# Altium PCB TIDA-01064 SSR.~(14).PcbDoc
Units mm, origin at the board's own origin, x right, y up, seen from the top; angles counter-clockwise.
Board outline 109.22 x 50.8 mm, 2 copper layers (Top Layer, Bottom Layer), stack 1.575 mm thick; 74 components, 26 nets, 146 pads, 5 vias.
Unrouted connection lines stored in the file: 92.
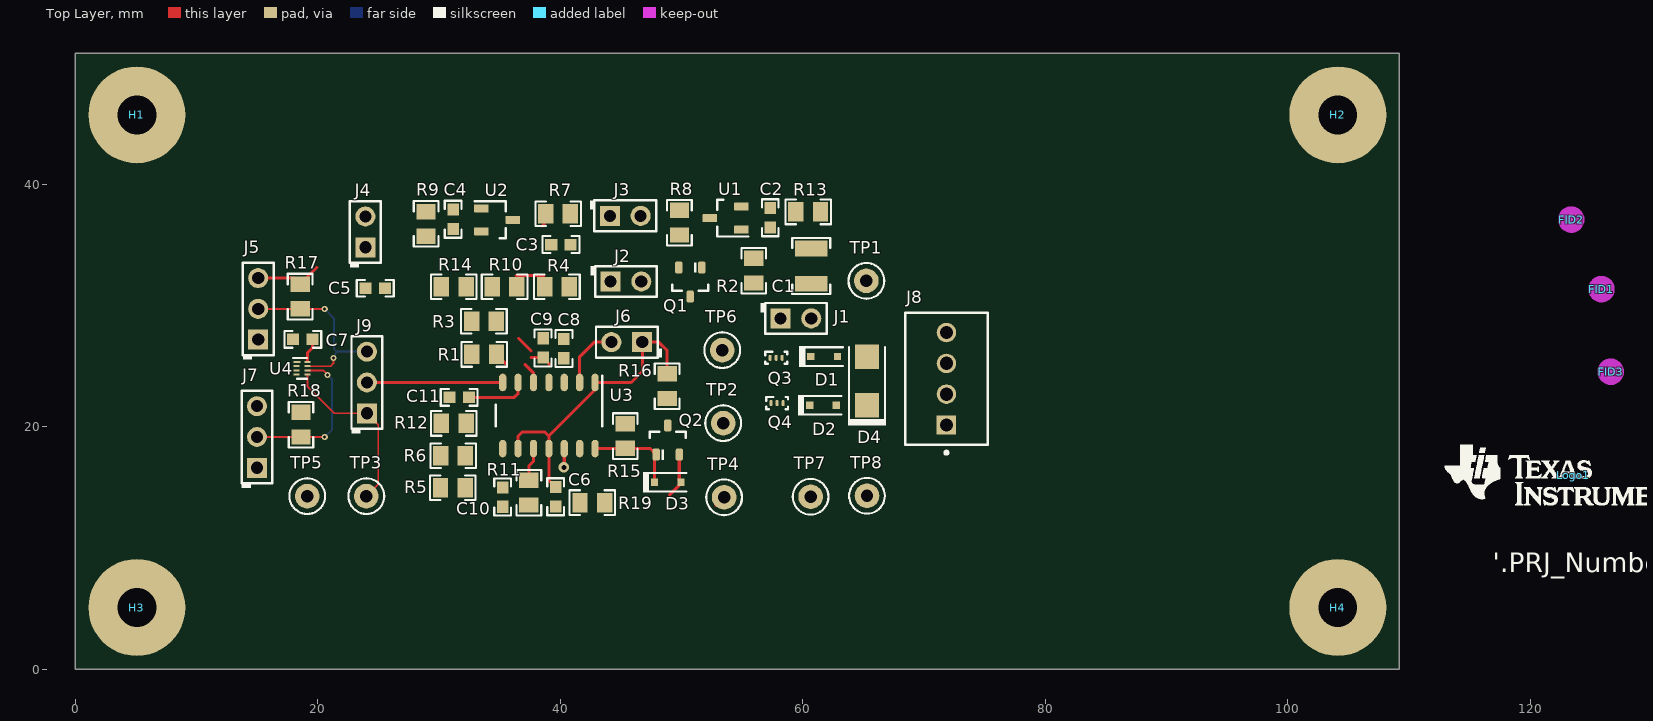
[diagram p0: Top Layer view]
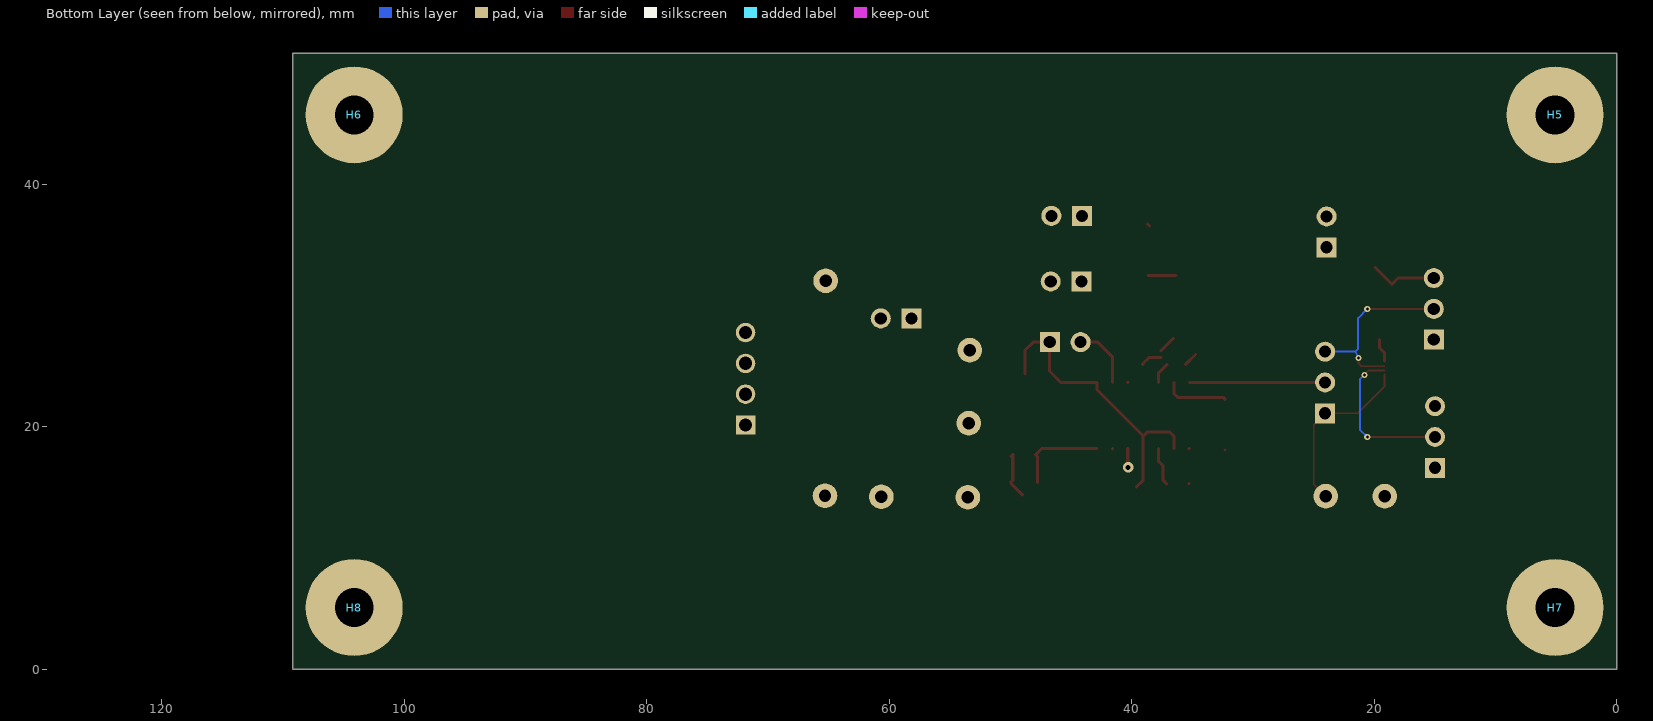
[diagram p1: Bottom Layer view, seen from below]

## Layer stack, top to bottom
Top Solder: solder mask 0.0102, Solder Resist, Dk 3.5
Top Layer: signal copper 0.0356
Dielectric1: core 1.5037, FR-4, Dk 4.8
Bottom Layer: signal copper 0.0356
Bottom Solder: solder mask 0.0102, Solder Resist, Dk 3.5

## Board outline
0,0 109.22,0 109.22,50.8 0,50.8

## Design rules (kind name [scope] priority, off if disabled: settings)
AcuteAngle [All] p1: minimum=4.50000000000000E+0001 checktracksonly=FALSE
AssemblyTestPointUsage [All] p1: valid=2
Clearance Clearance_BoardEdge_MountingHoles [OnCopper and InComponentClass('Mounting Holes') vs IsKeepOut] p1: gap=0.635
Clearance Clearance_BoardEdge_Poly [OnCopper and InPoly vs IsKeepOut] p2: gap=0.635
Clearance Clearance_BoardEdge [OnCopper and Not InComponentClass('Logo') and not InComponentClass('FiducialMark') and not InRegion(1000,500,4000,800) and Not IsKeepout vs IsKeepOut] p3: gap=0.635
Clearance Clearance_Poly [InPolygon] p4: gap=0.381
Clearance [All] p5: gap=0.203
ComponentClearance ComponentClearance_Shunt [InComponentClass('Header') vs InComponentClass('Shunt')] p1: gap=0 collisioncheckmode=3 verticalgap=0 showdistances=FALSE
ComponentClearance ComponentClearance_Logo [InComponentClass('Logo')] p2: gap=1.27 collisioncheckmode=3 verticalgap=0.254 showdistances=FALSE
ComponentClearance ComponentClearance_ScrewToNut [(HasFootprint('NY PMS 440 0025 PH')) vs (HasFootprint('Keystone_1902C'))] p3: gap=0.127 collisioncheckmode=3 verticalgap=0.254 showdistances=FALSE
ComponentClearance ComponentClearance_MountingHoles [InComponentClass('Mounting Holes')] p4: gap=6.35 collisioncheckmode=3 verticalgap=2540 showdistances=FALSE
ComponentClearance ComponentClearance_SmallPassives [HasFootprint('0201*') or HasFootprint('0402*') or HasFootprint('0508') or HasFootprint('0603*') or HasFootprint('0612') or HasFootprint('0805*') or HasFootprint('0815*') or HasFootprint('0830*') or HasFootprint('1206*') or HasFootprint('1210*') or HasFootprint('1808*') or HasFootprint('1812*') or HasFootprint('1825*') or HasFootprint('2010*') or HasFootprint('2220*') or HasFootprint('2225*') or HasFootprint('2512*') or HasFootprint('2728*') or HasFootprint('3518*') vs HasFootprint('0201*') or HasFootprint('0402*') or HasFootprint('0508') or HasFootprint('0603*') or HasFootprint('0612') or HasFootprint('0805*') or HasFootprint('0815*') or HasFootprint('0830*') or HasFootprint('1206*') or HasFootprint('1210*') or HasFootprint('1808*') or HasFootprint('1812*') or HasFootprint('1825*') or HasFootprint('2010*') or HasFootprint('2220*') or HasFootprint('2225*') or HasFootprint('2512*') or HasFootprint('2728*') or HasFootprint('3518*')] p5: gap=0.381 collisioncheckmode=3 verticalgap=0.254 showdistances=FALSE
ComponentClearance ComponentClearance_THtoSMT [IsThruComponent vs IsSMTComponent] p6: gap=1.27 collisioncheckmode=3 verticalgap=0.762 showdistances=FALSE
ComponentClearance ComponentClearance_THtoTH [IsThruComponent vs IsThruComponent] p7: gap=1.27 collisioncheckmode=3 verticalgap=0.762 showdistances=FALSE
ComponentClearance [All] p8: gap=1.016 collisioncheckmode=3 verticalgap=0.254 showdistances=FALSE
DiffPairsRouting [All] p1: maxlimit=2.54 minlimit=0.254 mostfreqgap=0.254 toplayer_minwidth=0.381 toplayer_maxwidth=0.381 toplayer_prefwidth=0.381 bottomlayer_minwidth=0.381 bottomlayer_maxwidth=0.381 bottomlayer_prefwidth=0.381 maxuncoupledlength=25.4
FabricationTestPointUsage TestPointUsage [All] p1: valid=2 allowmultiple=FALSE
FabricationTestpoint Testpoint [All] p1: side=3 testpointundercomponent=TRUE minsize=1.016 maxsize=2.54 preferedsize=1.524 minholesize=0 maxholesize=1.016 preferedholesize=0.813 testpointgrid=0.025 allowsidetop=TRUE allowsidebottom=TRUE usegrid=TRUE gridtolerance=0
FanoutControl Fanout_LCC [IsLCC] p1: bgadir=Out bgaviamode=Centered fanoutstyle=Auto fanoutdirection=Alternating viagrid=0.025 // Fanout_LCC (Default Rule)
FanoutControl Fanout_BGA [IsBGA] p2: bgadir=Out bgaviamode=Centered fanoutstyle=Auto fanoutdirection=Alternating viagrid=0.025 // Fanout_BGA (Default Rule)
FanoutControl Fanout_Default [All] p4: bgadir=Out bgaviamode=Centered fanoutstyle=Auto fanoutdirection=Alternating viagrid=0.025 // Fanout_Default (Default Rule)
FanoutControl Fanout_Small [(CompPinCount < 5)] p5: bgadir=Out bgaviamode=Centered fanoutstyle=Auto fanoutdirection=OutThenIn viagrid=0.025 // Fanout_Small (Default Rule)
HoleSize [All] p1: absolutevalues=TRUE maxlimit=6.375 minlimit=0.203 maxpercent=80.000 minpercent=20.000
MinimumAnnularRing MinimumAnnularRing_ThermalPadVias [IsVia and InAnyComponent] p1: minimumring=0.15
MinimumAnnularRing [All] p2: minimumring=0.229
MinimumSolderMaskSliver MinimumSolderMaskSliver_Logo [InComponentClass('Logo') vs InComponentClass('Logo')] p1: minsoldermaskwidth=0.018
MinimumSolderMaskSliver [All] p2: minsoldermaskwidth=0.1
PlaneClearance [All] p1: clearance=0.381
PlaneConnect [All] p1: planeconnectstyle=Direct reliefexpansion=0.254 reliefentries=4 reliefconductorwidth=0.254 reliefairgap=0.254
PolygonConnect [All] p1: connectstyle=Direct reliefconductorwidth=0.254 reliefentries=4 polygonreliefangle="90 Angle" airgapwidth=0.254
RoutingVias ThermalPadVias [IsVia and InAnyComponent] p1: holewidth=0.2 width=0.5 viastyle="Through Hole" minholewidth=0.2 minwidth=0.5 maxholewidth=0.33 maxwidth=0.6
RoutingVias [All] p2: holewidth=0.406 width=0.864 viastyle="Through Hole" minholewidth=0.2 minwidth=0.66 maxholewidth=1.016 maxwidth=1.651
SMDToCorner [All] p1: distance=30000
SilkToBoardRegionClearance [Not ((IsComment or IsDesignator) And (Hide <> 'False')) and not InRegion(1000,500,4000,800)] p1:
SilkToSilkClearance [All] p1: silktosilkclearance=0
SilkToSolderMaskClearance SilkscreenOverComponentPads [IsPad] p1: minsilkscreentomaskgap=0 clearancetoexposedcopper=TRUE
SolderMaskExpansion [All] p1: expansion=0.05
Width [All] p1: maxlimit=2.54 minlimit=0.152 preferedwidth=0.254 checkconnectedcopper=TRUE
14 further rules are at their usual default settings.

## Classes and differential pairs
component class "TIDA-01064 SSR_Relay": C1 C2 C3 C4 C6 C7 C8 C9 C10 C11 D1 D2 D3 D4 J1 J2 J3 J4 J5 J6 J7 J8 J9 Q1 Q2 Q3 Q4 R1 R2 R3 R4 R5 R6 R7 R8 R9 R10 R11 R12 R13 R14 R15 R16 R17 R18 R19 TP1 TP2 TP3 TP4 TP5 TP6 TP7 TP8 U1 U2 U3 U4
component class Header: J1 J2 J3 J4 J5 J6 J7 J9
component class "Mounting Holes": H1 H2 H3 H4
component class Logo: Logo1
component class "TIDA-01064 SSR_TID_Hardware": FID1 FID2 FID3 H1 H2 H3 H4 H5 H6 H7 H8 Logo1 ZZ1 ZZ2
component class FiducialMark: FID1 FID2 FID3
component class AssemblyNote: ZZ1 ZZ2

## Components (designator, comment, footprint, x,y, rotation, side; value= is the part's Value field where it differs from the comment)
C1 "C3225X7S2A335M200AB" 1210 60.706,33.249 r90 top
C2 "GRM1885C1H201JA01D" 0603 57.328,37.236 r90 top
C3 "GRM188R61E105KA12D" 0603 40.056,35.027 r180 top
C4 "GRM1885C1H201JA01D" 0603 31.166,37.109 r270 top
C5 "GRM188R61E105KA12D" 0603 24.74,31.42 r0 top
C6 "GRM188R61E105KA12D" 0603 39.624,14.224 r270 top
C7 "GRM188R71C104KA01D" 0603 18.771,27.203 r0 top
C8 "GRM188R71C104KA01D" 0603 40.31,26.441 r270 top
C9 "GRM188R71C104KA01D" 0603 38.583,26.492 r270 top
C10 "GRM188R71C104KA01D" 0603 35.255,14.199 r90 top
C11 "GRM188R71C104KA01D" 0603 31.666,22.42 r0 top
D1 "1N4448WX-TP" sod-323 61.773,25.781 r0 top
D2 "1N4448WX-TP" sod-323 61.671,21.768 r0 top
D3 "1N4448WX-TP" sod-323 48.87,15.418 r0 top
D4 "SMAJ40CA" SMA 65.303,23.774 r90 top
FID1 "Fiducial" Fiducial10-20 125.882,31.344 r0 top
FID2 "Fiducial" Fiducial10-20 123.393,37.084 r0 top
FID3 "Fiducial" Fiducial10-20 126.644,24.536 r0 top
H1 "NY PMS 440 0025 PH" "NY PMS 440 0025 PH" 5.08,45.72 r0 top locked
H2 "NY PMS 440 0025 PH" "NY PMS 440 0025 PH" 104.14,45.72 r0 top locked
H3 "NY PMS 440 0025 PH" "NY PMS 440 0025 PH" 5.08,5.08 r0 top locked
H4 "NY PMS 440 0025 PH" "NY PMS 440 0025 PH" 104.14,5.08 r0 top locked
H5 "1902C" Keystone_1902C 5.08,45.72 r180 bottom locked
H6 "1902C" Keystone_1902C 104.14,45.72 r180 bottom locked
H7 "1902C" Keystone_1902C 5.08,5.08 r180 bottom locked
H8 "1902C" Keystone_1902C 104.14,5.08 r180 bottom locked
J1 "5-146278-2" TE_5-146278-2 59.436,28.931 r0 top
J2 "5-146278-2" TE_5-146278-2 45.415,31.979 r0 top
J3 "5-146278-2" TE_5-146278-2 45.364,37.389 r0 top
J4 "5-146278-2" TE_5-146278-2 23.927,36.068 r90 top
J5 "5-146278-3" TE_5-146278-3 15.088,29.718 r90 top
J6 "5-146278-2" TE_5-146278-2 45.491,26.975 r180 top
J7 "5-146278-3" TE_5-146278-3 14.987,19.152 r90 top
J8 "282834-4" TEC_282834-4 71.857,23.952 r90 top
J9 "5-146278-3" TE_5-146278-3 24.054,23.647 r90 top
Logo1 "Texas Instruments" TI_Stacked_Overlay_Small 123.571,16.002 r0 top
Q1 "MMBTA05LT1G" SOT-23 50.724,31.928 r270 top
Q2 "MMBT3904LT1G" SOT-23 48.87,18.898 r90 top
Q3 "CSD18541F5" YJK0003A 57.81,25.679 r0 top
Q4 "CSD18541F5" YJK0003A 57.887,21.946 r0 top
R1 "CRCW080510M0FKEA" 0805_HV 33.724,25.959 r0 top
R2 "CRCW0805205KFKEA" 0805_HV 55.956,32.868 r270 top
R3 "CRCW08053M09FKEA" 0805_HV 33.706,28.702 r0 top
R4 "CRCW080510M0FKEA" 0805_HV 39.726,31.547 r0 top
R5 "CRCW080510M0FKEA" 0805_HV 31.14,14.961 r180 top
R6 "RC0805JR-0733ML" 0805_HV 31.166,17.602 r180 top
R7 "CRCW0805100KFKEA" 0805_HV 39.827,37.567 r0 top
R8 "CRCW08053M74FKEA" 0805_HV 49.835,36.83 r270 top
R9 "CRCW0805806KFKEA" 0805_HV 28.931,36.728 r90 top
R10 "CRCW08057M50FKEA" 0805_HV 35.408,31.547 r0 top
R11 "CRCW08054M32FKEA" 0805_HV 37.414,14.554 r90 top
R12 "CRCW08056M49FKEA" 0805_HV 31.217,20.269 r0 top
R13 "CRCW08051M30FKEA" 0805_HV 60.452,37.719 r180 top
R14 "CRCW08052M80FKEA" 0805_HV 31.217,31.547 r180 top
R15 "CRCW080590K9FKEA" 0805_HV 45.364,19.228 r90 top
R16 "CRCW08051M82FKEA" 0805_HV 48.819,23.343 r270 top
R17 "CRCW0805124KFKEA" 0805_HV 18.542,30.734 r90 top
R18 "CRCW0805124KFKEA" 0805_HV 18.618,20.168 r90 top
R19 "CRCW08050000Z0EA" 0805_HV 42.647,13.741 r0 top
TP1 "5001" Keystone5001 65.253,32.029 r0 top
TP2 "5001" Keystone5001 53.442,20.295 r0 top
TP3 "5001" Keystone5001 24.007,14.272 r0 top
TP4 "5001" Keystone5001 53.518,14.173 r0 top
TP5 "5001" Keystone5001 19.131,14.272 r0 top
TP6 "5001" Keystone5001 53.365,26.314 r0 top
TP7 "5001" Keystone5001 60.655,14.224 r0 top
TP8 "5001" Keystone5001 65.303,14.3 r0 top
U1 "ATL431AIDBZR" DBZ0003A_M 53.645,37.211 r180 top
U2 "ATL431AIDBZR" DBZ0003A_M 34.798,37.059 r0 top
U3 "LP339D" D0014A_N 39.065,20.922 r270 top
U4 "SN74AUP1G74DQER" DQE0008A 18.694,24.816 r0 top
ZZ1 "These assemblies are ESD sensitive, ESD precautions shall be observed." AssemblyNote 4.699,97.259 r0 top
ZZ2 "These assemblies must be clean and free from flux and all contaminants. Use of no clean flux is not acceptable." AssemblyNote 4.699,95.01 r0 top
ZZ3 "These assemblies must comply with workmanship standards IPC-A-610 Class 2, unless otherwise specified." AssemblyNote 4.699,92.761 r0 top

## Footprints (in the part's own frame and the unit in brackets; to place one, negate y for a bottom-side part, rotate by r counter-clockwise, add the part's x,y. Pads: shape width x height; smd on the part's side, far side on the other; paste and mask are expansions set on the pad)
0603 [mm] "0603 from SM-752 data"
  rect 1x0.95 smd: 1(-0.8,0) 2(0.8,0)
  silkscreen extent -1.52,-0.69 1.52,0.69, body extent -0.87,-0.47 0.87,0.47, height 1
0805_HV [mil] "0805 with 30mil clearance between pads"
  rect 50x63 smd: 1(-40,0) 2(40,0)
  silkscreen extent -74,-40 74,40, body extent -43,-29 43,29, height 57
1210 [mm] "1210 from SM-752 data"
  rect 1.3x2.7 smd: 1(-1.45,0) 2(1.45,0)
  silkscreen extent -2.32,-1.57 2.32,1.57, body extent -1.7,-1.35 1.7,1.35, height 1.35
AssemblyNote [mm] "Assembly Note"
D0014A_N [mm] "SOIC, 14-Leads, Body 8.7x3.9mm, Pitch 1.27mm, IPC Medium Density"
  oval 1.45x0.6 smd: 1(-2.725,3.81) 2(-2.725,2.54) 3(-2.725,1.27) 4(-2.725,0) 5(-2.725,-1.27) 6(-2.725,-2.54) 7(-2.725,-3.81) 8(2.725,-3.81) 9(2.725,-2.54) 10(2.725,-1.27) 11(2.725,0) 12(2.725,1.27) 13(2.725,2.54) 14(2.725,3.81)
  silkscreen extent -3.3,-4.4 0.9,4.4, body extent -3.02,-4.32 3.02,4.32, height 1.6
DBZ0003A_M [mm] "SOT23, 3-Leads, Body 2.9x1.3mm, Pitch 0.95mm, Lead Span 2.4mm, IPC Low Density"
  rrect15% 1.2x0.65 smd: 1(-1.3,0.95) 2(-1.3,-0.95) 3(1.3,0)
  silkscreen extent -1.85,-1.5 0.7,1.53, body extent -1.26,-1.46 1.26,1.46, height 0.98
DQE0008A [mm] "SON, 8-Leads, Body 1.4x1mm, Pitch 0.35mm, TI Recommended"
  rect 0.6x0.16 smd mask+0: 1(-0.4,0.525)
  rect 0.5x0.16 smd mask+0: 2(-0.45,0.175) 3(-0.45,-0.175) 4(-0.45,-0.525) 5(0.45,-0.525) 6(0.45,-0.175) 7(0.45,0.175) 8(0.45,0.525)
  silkscreen extent -0.7,-0.85 0.4,0.85, body extent -0.53,-0.72 0.53,0.73, height 0.41
Fiducial10-20 [mm]
  round 1 smd mask+0.5: 1(0,0)
  Top Layer keep-out circle w1.178: c0,0 r0.5
Keystone5001 [mil] "For Keystone 500x miniature loop terminals"
  round 80 hole 40: 1(0,0)
  silkscreen extent -58,-58 58,58, body extent -49,-49 49,49, height 182
Keystone_1902C [mm] "Hex Standoff, 4-40 threaded, nylon"
  body extent -3.68,-3.2 3.71,3.2, height 12.73
"NY PMS 440 0025 PH" [mm] "4-40 nylon screw and mounting hole"
  round 8 hole 3.2: 1(0,0)
  body extent -3.3,-3.3 3.3,3.3, height 2.69
SMA [mm] "Molded Diode, 2-Leads, Body 4.3x2.6mm, IPC Medium Density, based on OnSemi component dimensions and land pattern"
  rect 2x2 smd: 1(-2,0) 2(2,0)
  silkscreen extent -3.66,-1.57 2.79,1.57, body extent -2.6,-1.3 2.6,1.3, height 2.42
sod-323 [mm] "NXP recommended land pattern"
  rect 0.6x0.6 smd paste-0.05: 1(-1.1,0) 2(1.1,0)
  silkscreen extent -2.06,-0.86 1.53,0.86, body extent -1.3,-0.67 1.3,0.68, height 1.1
SOT-23 [mm] "SOT23, 3-Leads, Body 2.9x1.3mm, Pitch 0.95mm, Lead Span 2.5mm, IPC Medium Density"
  rrect50% 1x0.6 smd: 1(-1.2,0.95) 2(-1.2,-0.95) 3(1.2,0)
  silkscreen extent -1.63,-1.5 0.7,1.5, body extent -1.16,-1.45 1.21,1.45, height 1
TE_5-146278-2 [mm] "TE CONNECTIVITY"
  rect 1.65x1.65 hole 1: 1(-1.27,0)
  round 1.65 hole 1: 2(1.27,0)
  silkscreen extent -2.92,-1.27 2.54,1.27, body extent -2.41,-1.17 2.41,1.17, height 8.13
TE_5-146278-3 [mm] "TE CONNECTIVITY"
  rect 1.65x1.65 hole 1: 1(-2.54,0)
  round 1.65 hole 1: 2(0,0) 3(2.54,0)
  silkscreen extent -4.19,-1.27 3.81,1.27, body extent -3.68,-1.17 3.68,1.17, height 8.13
TEC_282834-4 [mm] "TEC"
  rect 1.6x1.6 hole 1.1: 1(-3.81,0)
  round 1.6 hole 1.1: 2(-1.27,0) 3(1.27,0) 4(3.81,0)
  silkscreen extent -6.2,-3.4 5.44,3.4, body extent -5.31,-3.25 5.31,3.25, height 10.02
TI_Stacked_Overlay_Small [mm]
  silkscreen extent -10.63,-2.49 10.63,2.49
YJK0003A [mm] "SMD, 3-Leads, Body 1.49x0.73mm"
  rrect80% 0.25x0.49 smd paste-0.05 mask-0.05: 1(-0.5,0) 2(0,0) 3(0.5,0)
  silkscreen extent -0.9,-0.5 0.9,0.5, body extent -0.75,-0.37 0.74,0.36, height 0.35

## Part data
C1: "CAP, CERM, 3.3 µF, 100 V, +/- 20%, X7S, 1210"
C2 C4: "CAP, CERM, 200 pF, 50 V, +/- 5%, C0G/NP0, 0603"
C3 C5 C6: "CAP, CERM, 1 µF, 25 V, +/- 10%, X5R, 0603"
C7 C8 C9 C10 C11: "CAP, CERM, 0.1 µF, 16 V, +/- 10%, X7R, 0603"
D1 D2 D3: "Diode, Switching, 75 V, 0.25 A, SOD-323"
D4: "Diode, TVS, Bi, 40 V, 400 W, SMA"
FID1 FID2 FID3: "Fiducial mark.  There is nothing to buy or mount."
H1 H2 H3 H4: "Machine Screw, Round, #4-40 x 1/4, Nylon, Philips panhead"
H5 H6 H7 H8: "Standoff, Hex, 0.5\"L #4-40 Nylon"
J1 J2 J3 J4 J6: "Header, 100mil, 2x1, Tin, TH"
J5 J7 J9: "Header, 100mil, 3x1, Tin, TH"
J8: "Terminal Block, 100mil, 4X1 TH"
Logo1: library part TI_Logo, "Texas Instrument Corporate Signature"
Q1: library part "MMBTA05LT1G, ON Semiconductor", "Transistor, NPN, 60 V, 0.5 A, AEC-Q101, SOT-23"
Q2: library part "MMBT3904LT1G, ON Semiconductor", "Transistor, NPN, 40 V, 0.2 A, SOT-23"
Q3 Q4: "MOSFET, N-CH, 60 V,  A, PICOSTAR-3"
R1 R4 R5: "RES, 10.0 M, 1%, 0.125 W, 0805"
R2: "RES, 205 k, 1%, 0.125 W, 0805"
R3: "RES, 3.09 M, 1%, 0.125 W, 0805"
R6: "RES, 33 M, 5%, 0.125 W, 0805"
R7: "RES, 100 k, 1%, 0.125 W, 0805"
R8: "RES, 3.74 M, 1%, 0.125 W, 0805"
R9: "RES, 806 k, 1%, 0.125 W, 0805"
R10: "RES, 7.50 M, 1%, 0.125 W, 0805"
R11: "RES, 4.32 M, 1%, 0.125 W, 0805"
R12: "RES, 6.49 M, 1%, 0.125 W, 0805"
R13: "RES, 1.30 M, 1%, 0.125 W, 0805"
R14: "RES, 2.80 M, 1%, 0.125 W, 0805"
R15: "RES, 90.9 k, 1%, 0.125 W, 0805"
R16: "RES, 1.82 M, 1%, 0.125 W, 0805"
R17 R18: "RES, 124 k, 1%, 0.125 W, 0805"
R19: "RES, 0, 5%, 0.125 W, 0805"
TP1 TP2 TP3 TP4 TP5 TP6 TP7 TP8: "Test Point, Miniature, Black, TH"
U1 U2: "2.5V Low Iq Adjustable Precision Shunt Regulator, DBZ0003A"
U3: "Quad, Low-Power, General Purpose Differential Comparator, D0014A"
U4: "LOW-POWER SINGLE POSITIVE-EDGE-TRIGGERED D-TYPE FLIP-FLOP WITH CLEAR AND PRESET, DQE0008A"
ZZ1 ZZ2 ZZ3: library part AssemblyNote

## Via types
v1: diameter 0.508, hole 0.254, Top Layer to Bottom Layer, 4 vias
v2: diameter 0.864, hole 0.406, Top Layer to Bottom Layer, 1 vias

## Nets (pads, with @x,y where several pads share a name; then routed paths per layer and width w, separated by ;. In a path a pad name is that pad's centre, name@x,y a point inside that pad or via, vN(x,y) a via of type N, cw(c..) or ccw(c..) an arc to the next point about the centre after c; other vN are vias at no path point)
3.3V: C5.1 C7.2 J4.1 J5.3 J7.3 R17.2 R18.2 U4.8 | length 7.6
  Top Layer w0.254: J5.3 18.034,32.258 R17.2 19.939,33.147 ; U4.8@19.144,25.401 19.144,26.074 19.571,26.5 C7.2
10V: C3.1 C8.2 J3.1 Q2.3 R4.2 R5.2 R6.2 R7.2 R15.2 R16.2 U3.3 | length 0
  Top Layer w0.254: U3.3@40.31,23.672 U3.3
GND: C1.2 C3.2 C5.2 C6.2 C7.1 C8.1 C9.1 C10.1 C11.1 J5.1 J7.1 Q3.2 Q4.3 R3.1 R10.1 R11.1 R12.1 R13.1 R14.1 TP5.1 TP6.1 TP7.1 U1.3 U2.3 U3.12 U4.1 U4.2 U4.4 | length 1.6
  Top Layer w0.254: v2(40.31,16.637) 40.335,16.662 U3.12
HV1: D1.2 D4.2 J8.3 J8.4 Q3.3 TP1.1
HV2: D2.2 D4.1 J8.1 J8.2 Q4.2 TP8.1
NetC1_1: C1.1 J1.1 J2.2 Q1.3 R2.2
NetC2_1: C2.1 Q1.1 R2.1 U1.1
NetC2_2: C2.2 R8.1 R13.2 U1.2
NetC4_1: C4.1 J4.2 R7.1 R9.2 U2.1 | length 0.2
  Top Layer w0.254: 38.542,36.561 38.71,36.728
NetC4_2: C4.2 R9.1 R14.2 U2.2
NetC6_1: C6.1 J6.1 R16.1 U3.1 U3.9 U3.11 | length 25.2
  Top Layer w0.254: U3.9 36.525,19.228 36.855,19.558 38.735,19.558 39.065,19.228 ; C6.1 39.065,15.583 U3.11 39.065,19.228 ; R16.1 48.819,26.289 48.133,26.975 J6.1 46.787,26.949 46.787,24.587 45.846,23.647 U3.1 42.875,23.038 39.065,19.228
NetD1_1: D1.1 D2.1 J1.2
NetD3_1: D3.1 Q2.1 R15.1 TP2.1 U3.14 | length 7.6
  Top Layer w0.254: U3.14 45.349,18.197 R15.1 47.405,18.212 Q2.1 47.77,17.548 D3.1 ; TP2.1@53.416,20.269 TP2.1
NetD3_2: D3.2 Q2.2 Q3.1 Q4.1 R19.2 TP4.1 | length 5
  Top Layer w0.254: 48.997,14.351 49.97,15.324 D3.2 49.82,15.568 Q2.2 Q2.2@49.97,17.548 ; TP4.1@52.832,13.487 TP4.1
NetJ2_1: J2.1 R1.1
NetJ3_2: J3.2 Q1.2 R8.2
NetJ6_2: J6.2 U3.2 | length 5.2
  Top Layer w0.254: U3.2 41.605,25.781 42.799,26.975 J6.2
NetJ9_1: J9.1 TP3.1 U4.5 | length 14.4
  Top Layer w0.152: U4.5 19.144,23.324 21.361,21.107 J9.1 24.994,20.168 24.994,15.258 TP3.1
NetJ9_2: J9.2 U3.7 | length 11.2
  Top Layer w0.254: J9.2 U3.7
NetR19_1: R19.1 U3.13 | length 0
  Top Layer w0.254: U3.13@41.58,18.171 U3.13
OFF#: J7.2 R18.1 U4.6 | length 12.9
  Top Layer w0.152: J7.2 R18.1 v1(20.574,19.152) ; U4.6 20.444,24.641 v1(20.815,24.27)
  Bottom Layer w0.152: v1(20.574,19.152) 21.184,19.761 21.184,23.901 v1(20.815,24.27)
ON#: J5.2 J9.3 R17.1 U4.7 | length 15.2
  Top Layer w0.152: J5.2 R17.1 v1(20.574,29.718) ; U4.7 21.054,24.991 21.285,25.222 v1(21.285,25.679)
  Bottom Layer w0.152: v1(20.574,29.718) 21.336,28.956 21.336,26.416 21.565,26.187 ; v1(21.285,25.679) 21.565,26.187 ; J9.3 21.565,26.187
VREF1: C9.2 R4.1 R10.2 U3.4 | length 5.5
  Top Layer w0.254: 36.373,32.487 38.659,32.487 ; 36.576,27.28 37.592,26.264 ; 37.592,25.705 38.57,25.705 C9.2 39.111,25.163 39.065,25.117
VREF2: C10.2 R5.1 R11.2 U3.8 U3.10 | length 3.3
  Top Layer w0.254: U3.8 U3.8@35.292,18.16 ; C10.2@35.28,15.291 C10.2@35.292,15.279 ; R11.2@37.123,15.279 R11.2 37.414,16.764 37.795,17.145 U3.10
VREF3: C11.2 R6.1 R12.2 U3.6 | length 5.3
  Top Layer w0.254: C11.2@32.301,22.255 C11.2 36.212,22.42 36.525,22.733 U3.6
VUVLO: R1.2 R3.2 U3.5 | length 3
  Top Layer w0.254: R1.2 35.553,25.146 ; 37.084,25.146 37.776,24.454 37.795,24.454 U3.5
pads on no net: FID1.1 FID2.1 FID3.1 H1.1 H2.1 H3.1 H4.1 U4.3

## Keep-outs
Keep-Out Layer:
  text ".Layer_Name" at 14.656,-21.806 h1.52

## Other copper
Top Layer:
  text ".Layer_Name" at 14.656,-21.806 h1.52
Bottom Layer:
  text ".Layer_Name" at 14.656,-21.806 h1.52

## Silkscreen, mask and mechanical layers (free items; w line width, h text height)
Top Overlay:
  text "'.PRJ_Number' .PCB_Rev" at 116.916,7.468 h2.75
  text ".Layer_Name" at 14.656,-21.806 h1.52
Bottom Overlay:
  text ".Layer_Name" at 14.656,-21.806 h1.52
Top Paste:
  text ".Layer_Name" at 14.656,-21.806 h1.52
Bottom Paste:
  text ".Layer_Name" at 14.656,-21.806 h1.52
Top Solder:
  text ".Layer_Name" at 14.656,-21.806 h1.52
  text ".Layer_Name" at 14.656,-21.806 h1.52
Bottom Solder:
  text ".Layer_Name" at 14.656,-21.806 h1.52
Drill Guide:
  text ".Layer_Name" at 14.656,-21.806 h1.52
M1 Board Outline:
  the board outline again, w0.254
  text ".Layer_Name" at 14.656,-21.806 h1.52
M2 Board Dimensions:
  rectangle: 0,-6.985 3.175,-3.81
  rectangle: 3.175,-10.16 12.7,-6.985
  lines w0.178: 0,-6.985 25.4,-6.985 ; 3.175,-10.16 3.175,-3.81 ; 6.35,-10.16 6.35,-3.81 ; 12.7,-10.16 12.7,-3.81 ; 19.05,-10.16 19.05,-3.81 ; 0,-10.16 25.4,-10.16 25.4,-3.81 0,-3.81 0,-10.16
  text ".Layer_Name" at 14.656,-21.806 h1.52
M3 3D STEP Top:
  text ".Layer_Name" at 14.656,-21.806 h1.52
M4 3D STEP Bottom:
  text ".Layer_Name" at 14.656,-21.806 h1.52
M5 Assembly Top:
  lines w0.254: -7.417,-23.626 160.223,-23.626 ; -7.417,-18.462 160.274,-18.462 ; -7.417,-13.297 -7.417,-28.791 94.31,-28.791 160.274,-28.791 160.274,-13.297 -7.404,-13.297 -7.404,-28.791 32.614,-28.791 ; 55.194,-28.791 55.194,-13.297 ; 87.376,-18.462 87.376,-13.297 ; 108.712,-18.462 108.712,-13.297 ; 124.511,-28.956 124.511,-23.804
  text "COMPONENTS MARKED 'DNP' SHOULD NOT BE POPULATED." at 29.299,-8.09 h1.52
  text "ASSEMBLY VARIANT:" at 29.286,-11.024 h1.52
  text ".VariantName" at 55.601,-11.024 h1.52
  text "PCB VIEWED FROM TOP SIDE" at -5.804,-16.654 h1.52
  text "BOARD #:" at 57.099,-16.654 h1.52
  text ".PRJ_Number" at 70.955,-16.654 h1.52
  text "REV:" at 92.405,-16.654 h1.52
  text ".PCB_Rev" at 99.809,-16.654 h1.52
  text "SVN REV:" at 113.69,-16.654 h1.52
  text ".VersionControl_RevNumber" at 126.543,-16.654 h1.52
  text "TID #:" at 57.099,-21.819 h1.52
  text ".TID" at 70.955,-21.819 h1.52
  text "PLOT NAME =" at -5.804,-27.034 h1.52
  text ".plot_File_Name" at 14.656,-27.034 h1.52
  text "GENERATED    :" at 57.15,-27.034 h1.52
  text ".Print_Date" at 79.235,-27.034 h1.52
  text ".Print_Time" at 97.752,-27.034 h1.52
  text "TEXAS INSTRUMENTS" at 129.87,-27.034 h1.52
M6 Assembly Bottom:
  lines w0.254: -7.429,-18.474 160.261,-18.474 ; -7.379,-23.639 160.261,-23.639 ; 28.334,-28.969 28.334,-23.817 ; 44.133,-18.474 44.133,-13.31 ; 65.468,-18.474 65.468,-13.31 ; 97.65,-28.804 97.65,-13.31 ; 120.231,-28.804 160.249,-28.804 160.249,-13.31 -7.429,-13.31 -7.429,-28.804 58.534,-28.804 160.261,-28.804 160.261,-13.31
  text "COMPONENTS MARKED 'DNP' SHOULD NOT BE POPULATED." at 154.991,-8.077 h1.52
  text ".VariantName" at 128.473,-11.024 h1.52
  text "ASSEMBLY VARIANT:" at 154.864,-11.024 h1.52
  text ".VersionControl_RevNumber" at 26.302,-16.667 h1.52
  text "SVN REV:" at 39.154,-16.667 h1.52
  text ".PCB_Rev" at 53.035,-16.667 h1.52
  text "REV:" at 60.439,-16.667 h1.52
  text ".PRJ_Number" at 81.89,-16.667 h1.52
  text "BOARD #:" at 95.745,-16.667 h1.52
  text "PCB VIEWED FROM BOTTOM SIDE" at 158.648,-16.667 h1.52
  text ".TID" at 81.89,-21.831 h1.52
  text "TID #:" at 95.745,-21.831 h1.52
  text "TEXAS INSTRUMENTS" at 22.974,-27.047 h1.52
  text ".Print_Time" at 55.093,-27.047 h1.52
  text ".Print_Date" at 73.609,-27.047 h1.52
  text "GENERATED    :" at 95.694,-27.047 h1.52
  text ".plot_File_Name" at 138.189,-27.047 h1.52
  text "PLOT NAME =" at 158.648,-27.047 h1.52
M9 Title Sheet:
  drawing of 57 lines, arcs and shapes, not listed
  text "1" at 18.792,204.127 h1.78
  text "2" at 82.182,204.127 h1.78
  text "3" at 145.411,204.127 h1.78
  text "4" at 209.08,204.127 h1.78
  text "5" at 272.555,204.127 h1.78
  text "6" at 336.182,204.127 h1.78
  text "A" at -10.579,175.095 h1.78
  text "A" at 365.341,175.095 h1.78
  text "B" at -10.579,114.643 h1.78
  text "B" at 365.341,114.643 h1.78
  text "C" at -10.579,54.318 h1.78
  text "C" at 365.341,54.318 h1.78
  text "PROJECT TITLE:" at 288.125,7.048 h1.14
  text ".PRJ_Title" at 289.395,3.662 h1.78
  text "DESIGNED FOR:" at 288.125,-0.597 h1.14
  text ".PRJ_Customer" at 289.395,-4.153 h1.78
  text "D" at -10.579,-5.88 h1.78
  text "D" at 365.341,-5.88 h1.78
  text "FILE NAME:" at 288.125,-8.217 h1.14
  text ".PCB_File_Name_No_Path" at 289.395,-11.265 h1.78
  text "Texas Instruments (TI) and/or its licensors do not warrant the accuracy or completeness of this specification" at 161.9,-15.376 h1.14
  text "ENGINEER:" at 288.125,-15.583 h1.14
  text "LAYOUT BY:" at 326.352,-15.583 h1.14
  text "or any information contained therein. TI and/or its licensors do not warrant that this design will meet" at 160.757,-18.237 h1.14
  text ".PRJ_Engineer" at 289.395,-19.52 h1.78
  text ".PCB_Layout" at 327.635,-19.52 h1.78
  text "the specifications, will be suitable for your application or fit for any particular purpose, or will operate in" at 160.757,-21.099 h1.14
  text ".Layer_Name" at 14.656,-21.806 h1.52
  text "ALTIUM DESIGNER VERSION:" at 326.352,-23.457 h1.14
  text "an implementation. TI and/or its licensors do not warrant that the design is production worthy. You should" at 160.757,-23.961 h1.14
  text "completely validate and test your design implementation to confirm the system functionality for your application." at 161.9,-26.822 h1.14
  text ".print_Scale" at 289.395,-26.843 h1.78
  text ".Application_BuildNumber" at 327.635,-26.843 h1.78
  text "1" at 18.792,-32.093 h1.78
  text "2" at 82.182,-32.093 h1.78
  text "3" at 145.411,-32.093 h1.78
  text "4" at 209.08,-32.093 h1.78
  text "5" at 272.555,-32.093 h1.78
  text "6" at 336.182,-32.093 h1.78
M10 Fab Notes:
  drawing of 173 lines, arcs and shapes, not listed
  text "DESIGN INFORMATION" at 314.402,157.505 h1.52
  text "MIN. TRACK WIDTH:" at 298.03,152.933 h1.52
  text "8" at 325.874,152.933 h1.52
  text "MIL" at 329.805,152.933 h1.52
  text "MIN. CLEARANCE:" at 298.03,149.581 h1.52
  text "0.2" at 324.35,149.581 h1.52
  text "mm" at 329.805,149.581 h1.52
  text "MIN. VIA PAD SIZE:" at 298.03,146.228 h1.52
  text "24" at 325.113,146.228 h1.52
  text "MIL" at 329.805,146.228 h1.52
  text "0.05mm (2MIL)" at 315.683,142.628 h1.52
  text "MINIMUM ANNULAR RING" at 289.667,142.52 h1.52
  text "EXTERNAL" at 333.666,142.52 h1.52
  text "PER" at 294.747,139.522 h1.52
  text "IPC-D-275 CLASS 2 LEVEL C" at 300.335,139.522 h1.52
  text "MIL, HOLES" at 338.136,136.67 h1.52
  text "+/-" at 328.168,136.652 h1.52
  text "+/-" at 349.86,136.652 h1.52
  text "REGISTRATION TOLERANCES:" at 289.667,136.525 h1.52
  text "METAL" at 320.142,136.525 h1.52
  text "5" at 334.777,136.525 h1.52
  text "3" at 355.935,136.525 h1.52
  text "MIL" at 358.888,136.525 h1.52
  text "+/-" at 349.86,133.655 h1.52
  text "HOLE SIZE TOLERANCE (UNLESS OTHERWISE SPECIFIED):" at 289.667,133.528 h1.52
  text "3" at 355.935,133.528 h1.52
  text "MIL" at 358.888,133.528 h1.52
  text "MATERIAL:" at 287.768,128.208 h1.52
  text "FR-4 High Tg" at 312.824,124.643 h1.52
  text "FR-408" at 298.462,124.425 h1.52
  text "OTHER" at 336.257,124.425 h1.52
  text "X" at 308.889,124.333 h1.52
  text "62 MIL (1.6mm) +/-10%" at 306.592,120.292 h1.52
  text "THICKNESS:" at 289.667,120.184 h1.52
  text "X" at 303.337,120.184 h1.52
  text "OTHER" at 339.229,120.184 h1.52
  text "TOLERANCE:" at 289.667,116.17 h1.52
  text "X" at 310.986,116.17 h1.52
  text "ANSI IPC-6012 TYPE 3 CLASS 2" at 315.734,116.17 h1.52
  text "OTHER +/-" at 315.734,112.208 h1.52
  text "BOW & TWIST:" at 289.667,108.22 h1.52
  text "X" at 310.986,108.22 h1.52
  text "ANSI IPC-6012 TYPE 3 CLASS 2" at 315.734,108.22 h1.52
  text "OTHER +/-" at 315.734,104.194 h1.52
  text "DRILLING:" at 287.768,100.676 h1.52
  text "REFERENCE:" at 289.667,97.705 h1.52
  text "X" at 306.132,97.705 h1.52
  text "AS SHOWN" at 310.882,97.705 h1.52
  text "X" at 329.018,97.705 h1.52
  text "NC_DRILL FILES" at 332.498,97.705 h1.52
  text "PTH COPPER THICKNESS:" at 289.667,93.691 h1.52
  text "X" at 318.375,93.691 h1.52
  text "20-30 um" at 321.855,93.691 h1.52
  text "OTHER" at 340.067,93.691 h1.52
  text "BOARD FINISH:" at 287.768,89.653 h1.52
  text "SILKSCREEN:" at 291.711,86.656 h1.52
  text "X" at 315.81,86.656 h1.52
  text "TOP" at 319.01,86.656 h1.52
  text "X" at 328.764,86.656 h1.52
  text "BOTTOM" at 331.99,86.656 h1.52
  text "SILKSCREEN COLOR:" at 291.711,82.414 h1.52
  text "X" at 315.783,82.414 h1.52
  text "WHITE" at 319.01,82.414 h1.52
  text "OTHER" at 331.99,82.414 h1.52
  text "X" at 319.111,78.37 h1.52
  text "GREEN" at 322.338,78.37 h1.52
  text "OTHER" at 338.035,78.37 h1.52
  text "SOLDER RESIST COLOR:" at 291.711,78.096 h1.52
  text "X" at 319.111,74.052 h1.52
  text "MATTE" at 322.338,74.052 h1.52
  text "SEMI-GLOSS" at 338.023,74.036 h1.52
  text "IMMERSION GOLD (ENIG)" at 314.718,69.264 h1.52
  text "ENEPIG" at 348.691,69.18 h1.52
  text "SURFACE FINISH:" at 287.768,69.155 h1.52
  text "X" at 309.969,69.155 h1.52
  text "IMM. TIN/SILVER OR EQUIV" at 296.139,65.167 h1.52
  text "OTHER" at 332.498,65.167 h1.52
  text "ARRAY/PANEL:" at 287.768,60.621 h1.52
  text "CUT AND TRIM PER M1 BOARD OUTLINE" at 314.718,60.512 h1.52
  text "N.C. ROUTE" at 314.718,56.658 h1.52
  text "X" at 331.964,56.658 h1.52
  text "V. SCORE" at 336.714,56.658 h1.52
  text "CERTIFICATION:" at 287.768,53.178 h1.52
  text "MATERIALS AND WORKMANSHIP FOR ALL PCBS" at 306.183,53.178 h1.52
  text "TO MEET OR EXCEED THE REQUIREMENTS OF:" at 306.183,50.689 h1.52
  text "X" at 296.696,47.222 h1.52
  text "ANSI IPC-A-600F CLASS ->" at 300.227,47.222 h1.52
  text "X" at 341.859,47.222 h1.52
  text "2" at 344.88,47.222 h1.52
  text "1" at 336.879,47.184 h1.52
  text "3" at 353.872,47.184 h1.52
  text "X" at 317.373,43.171 h1.52
  text "RoHS" at 320.852,43.171 h1.52
  text "OTHER" at 337.22,43.171 h1.52
  text "PER ORDER" at 347.305,43.171 h1.52
  text "ALL BOARDS MUST MEET OR EXCEED UL94-V0 REQUIREMENTS." at 288.468,38.964 h1.52
  text "PCB MUST BEAR THE UL94V-0 UL REGISTERED MATERIAL ID NUMBER" at 288.468,35.916 h1.52
  text "ADDITIONAL REQUIREMENTS:" at 287.768,31.512 h1.52
  text "MICROSECTION:" at 289.667,28.591 h1.52
  text "YES" at 312.673,28.591 h1.52
  text "REQUIRED" at 334.555,24.625 h1.52
  text "BARE BOARD ELEC. TEST:" at 289.667,24.553 h1.52
  text "NONE" at 322.833,24.553 h1.52
  text "X" at 331.329,24.553 h1.52
  text "PER ORDER" at 349.592,24.553 h1.52
  text ".Layer_Name" at 14.656,-21.806 h1.52
M11 Gerber Information:
  lines w0.254: -7.417,-23.626 160.223,-23.626 ; -7.417,-18.462 160.274,-18.462 ; -7.417,-13.297 -7.417,-28.791 94.31,-28.791 160.274,-28.791 160.274,-13.297 -7.404,-13.297 -7.404,-28.791 32.614,-28.791 ; 55.194,-28.791 55.194,-13.297 ; 87.376,-18.462 87.376,-13.297 ; 108.712,-18.462 108.712,-13.297 ; 124.511,-28.956 124.511,-23.804
  text "ALL ARTWORK VIEWED FROM TOP SIDE" at -5.804,-16.654 h1.52
  text "BOARD #:" at 57.099,-16.654 h1.52
  text ".PRJ_Number" at 70.955,-16.654 h1.52
  text "REV:" at 92.405,-16.654 h1.52
  text ".PCB_Rev" at 99.809,-16.654 h1.52
  text "SVN REV:" at 113.69,-16.654 h1.52
  text ".VersionControl_RevNumber" at 126.543,-16.654 h1.52
  text "LAYER NAME =" at -5.804,-21.806 h1.52
  text "TID #:" at 57.099,-21.819 h1.52
  text ".TID" at 70.955,-21.819 h1.52
  text "PLOT NAME =" at -5.804,-27.034 h1.52
  text ".plot_File_Name" at 14.656,-27.034 h1.52
  text "GENERATED    :" at 57.15,-27.034 h1.52
  text ".Print_Date" at 79.235,-27.034 h1.52
  text ".Print_Time" at 97.752,-27.034 h1.52
  text "TEXAS INSTRUMENTS" at 129.87,-27.034 h1.52
M12 Stackup:
  drawing of 191 lines, arcs and shapes, not listed
  text "Layer" at 248.675,198.882 h1.52
  text "Name" at 259.086,198.882 h1.52
  text "Material" at 282.702,198.882 h1.52
  text "Thickness" at 304.54,198.882 h1.52
  text "Constant" at 321.046,198.882 h1.52
  text "Board Layer Stack" at 335.52,198.882 h1.52
  text "1" at 248.675,195.834 h1.52
  text "Top Overlay" at 259.086,195.834 h1.52
  text "2" at 248.675,192.786 h1.52
  text "Top Solder" at 259.086,192.786 h1.52
  text "Solder Resist" at 282.702,192.786 h1.52
  text "0.40mil" at 304.54,192.786 h1.52
  text "3.5" at 321.046,192.786 h1.52
  text "3" at 248.675,189.738 h1.52
  text "Top Layer" at 259.086,189.738 h1.52
  text "Copper" at 282.702,189.738 h1.52
  text "1.40mil" at 304.54,189.738 h1.52
  text "4" at 248.675,186.69 h1.52
  text "Dielectric1" at 259.086,186.69 h1.52
  text "FR-4" at 282.702,186.69 h1.52
  text "59.20mil" at 304.54,186.69 h1.52
  text "4.8" at 321.046,186.69 h1.52
  text "5" at 248.675,183.642 h1.52
  text "Bottom Layer" at 259.086,183.642 h1.52
  text "Copper" at 282.702,183.642 h1.52
  text "1.40mil" at 304.54,183.642 h1.52
  text "6" at 248.675,180.594 h1.52
  text "Bottom Solder" at 259.086,180.594 h1.52
  text "Solder Resist" at 282.702,180.594 h1.52
  text "0.40mil" at 304.54,180.594 h1.52
  text "3.5" at 321.046,180.594 h1.52
  text "7" at 248.675,177.546 h1.52
  text "Bottom Overlay" at 259.086,177.546 h1.52
  text ".Layer_Name" at 14.656,-21.806 h1.52
M13 Component Bodies Top:
  text ".Layer_Name" at 14.656,-21.806 h1.52
M14 Component Bodies Bottom:
  text ".Layer_Name" at 14.656,-21.806 h1.52
M15 Courtyards Top:
  text ".Layer_Name" at 14.656,-21.806 h1.52
M16 Courtyards Bottom:
  text ".Layer_Name" at 14.656,-21.806 h1.52
Drill Drawing:
  circle w0.254: c136.238,67.175 r0.702
  lines w0.254: 135.537,69.982 135.888,69.982 136.238,69.631 136.589,69.982 136.94,69.982 136.589,70.333 136.94,70.684 136.589,70.684 136.238,71.034 135.888,70.684 135.537,70.684 135.888,70.333 135.537,69.982 ; 135.537,74.192 136.94,74.192 136.238,72.789 135.537,74.192 ; 135.537,75.946 136.94,75.946 136.94,77.35 135.537,77.35 135.537,75.946 ; 135.537,79.104 136.238,79.455 136.94,79.104 136.589,79.806 136.94,80.508 136.238,80.157 135.537,80.508 135.888,79.806 135.537,79.104 ; 135.537,82.613 135.888,82.613 135.888,82.262 136.589,82.262 136.589,82.613 136.94,82.613 136.94,83.314 136.589,83.314 136.589,83.665 135.888,83.665 135.888,83.314 135.537,83.314 135.537,82.613
  lines w0.305: 134.264,65.526 216.344,65.526 ; 134.264,84.472 216.344,84.472 ; 142.846,62.368 142.846,87.63 ; 151.279,62.368 151.279,87.63 ; 167.448,62.368 167.448,87.63 ; 174.03,62.368 174.03,87.63 ; 183.559,62.368 183.559,87.63 ; 201.957,62.368 201.957,87.63 ; 134.264,62.368 216.344,62.368 216.344,87.63 134.264,87.63 134.264,62.368
  text "Symbol" at 136.159,85.42 h1.83
  text "Quantity" at 143.793,85.42 h1.83
  text "Finished Hole Size" at 152.226,85.42 h1.83
  text "Plated" at 168.395,85.42 h1.83
  text "Hole Type" at 174.977,85.42 h1.83
  text "Drill Layer Pair" at 184.506,85.42 h1.83
  text "Hole Tolerance" at 202.904,85.42 h1.83
  text "4" at 143.793,82.262 h1.52
  text "10.00mil (0.254mm)" at 152.226,82.262 h1.52
  text "PTH" at 168.395,82.262 h1.52
  text "Round" at 174.977,82.262 h1.52
  text "Top Layer - Bottom Layer" at 184.506,82.262 h1.52
  text "1" at 143.793,79.104 h1.52
  text "16.00mil (0.406mm)" at 152.226,79.104 h1.52
  text "PTH" at 168.395,79.104 h1.52
  text "Round" at 174.977,79.104 h1.52
  text "Top Layer - Bottom Layer" at 184.506,79.104 h1.52
  text "19" at 143.793,75.946 h1.52
  text "39.37mil (1.000mm)" at 152.226,75.946 h1.52
  text "PTH" at 168.395,75.946 h1.52
  text "Round" at 174.977,75.946 h1.52
  text "Top Layer - Bottom Layer" at 184.506,75.946 h1.52
  text "8" at 143.793,72.789 h1.52
  text "40.00mil (1.016mm)" at 152.226,72.789 h1.52
  text "PTH" at 168.395,72.789 h1.52
  text "Round" at 174.977,72.789 h1.52
  text "Top Layer - Bottom Layer" at 184.506,72.789 h1.52
  text "4" at 143.793,69.631 h1.52
  text "43.31mil (1.100mm)" at 152.226,69.631 h1.52
  text "PTH" at 168.395,69.631 h1.52
  text "Round" at 174.977,69.631 h1.52
  text "Top Layer - Bottom Layer" at 184.506,69.631 h1.52
  text "4" at 143.793,66.473 h1.52
  text "125.98mil (3.200mm)" at 152.226,66.473 h1.52
  text "PTH" at 168.395,66.473 h1.52
  text "Round" at 174.977,66.473 h1.52
  text "Top Layer - Bottom Layer" at 184.506,66.473 h1.52
  text "40 Total" at 143.793,63.315 h1.52
  text ".Layer_Name" at 14.656,-21.806 h1.52
M17 Embedded Cavity:
  text ".Layer_Name" at 14.656,-21.806 h1.52
M18 Embedded Assembly:
  text ".Layer_Name" at 14.656,-21.806 h1.52
M19 Embedded Keepout:
  text ".Layer_Name" at 14.656,-21.806 h1.52

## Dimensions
0,-10.16 to 25.4,-10.16 on M2 Board Dimensions
0,0 to 0,50.8 on M2 Board Dimensions
0,0 to 109.22,0 on M2 Board Dimensions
